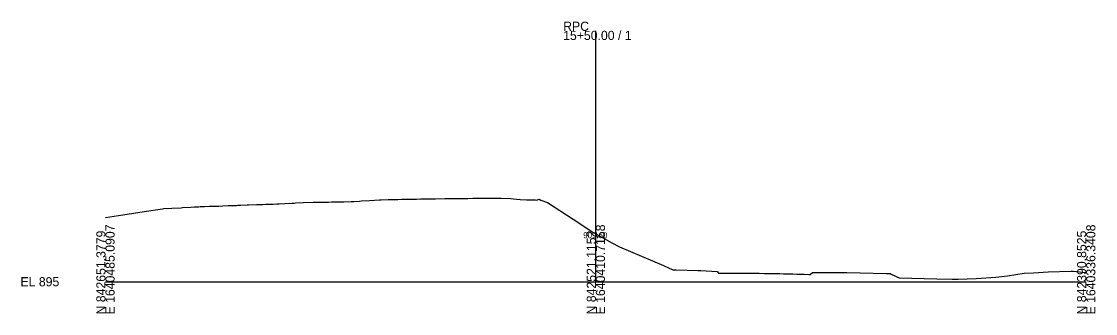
# Model space of a CAD drawing. Extents: x -26 to 1640245, y -10 to 842531.
# Drawn here: x 1274.3 to 1602.8, y 1490.3 to 1579.5 of the extents above; entities that cross this region are included whole.
import ezdxf

# ---------------------------------------------------------------- set-up
doc = ezdxf.new("R2010")
doc.units = 0
for name, color, linetype in [('Exist Cross Section Cell', 7, 'Continuous'), ('Exist XS Center Line Elevation Label', 7, 'Continuous'), ('Exist XS Ground Line', 7, 'Continuous')]:
    doc.layers.add(name, color=color, linetype=linetype)

msp = doc.modelspace()

# ---------------------------------------------------------------- linework, layer by layer
at = {"layer": 'Exist Cross Section Cell'}
for p, q in [((1450, 1500), (1450, 1576.62)), ((1300, 1500), (1450, 1500)), ((1450, 1500), (1600, 1500))]:
    msp.add_line(p, q, dxfattribs=at)
at = {"layer": 'Exist XS Ground Line'}
msp.add_lwpolyline([(1300, 1519.62), (1305.35, 1520.46), (1311.87, 1521.45), (1317.42, 1522.29), (1317.83, 1522.35), (1320.3, 1522.48), (1323.18, 1522.62), (1323.58, 1522.64), (1326.06, 1522.82), (1327.24, 1522.87), (1328.47, 1522.91), (1328.94, 1522.93), (1330.29, 1522.98), (1331.81, 1523.03), (1332.23, 1523.05), (1332.96, 1523.06), (1334.06, 1523.1), (1334.69, 1523.11), (1335.89, 1523.16), (1337.57, 1523.24), (1338.01, 1523.25), (1339.44, 1523.3), (1340.04, 1523.32), (1340.45, 1523.34), (1341.39, 1523.37), (1343.33, 1523.45), (1343.71, 1523.47), (1346.21, 1523.56), (1348.08, 1523.61), (1349.09, 1523.64), (1351.27, 1523.74), (1352.39, 1523.8), (1353.12, 1523.83), (1354.84, 1523.91), (1357.13, 1524.01), (1357.72, 1524.03), (1358.17, 1524.05), (1360.6, 1524.15), (1363.49, 1524.27), (1363.87, 1524.27), (1364.48, 1524.27), (1366.36, 1524.3), (1368.25, 1524.35), (1369.24, 1524.37), (1370.71, 1524.4), (1372.12, 1524.42), (1372.53, 1524.45), (1372.88, 1524.45), (1375.15, 1524.48), (1375.97, 1524.52), (1377.69, 1524.65), (1378.33, 1524.69), (1380.75, 1524.84), (1383.85, 1525), (1384.32, 1525.01), (1386.51, 1525.09), (1388.42, 1525.13), (1389.39, 1525.14), (1390.68, 1525.17), (1392.27, 1525.2), (1393.46, 1525.22), (1395.15, 1525.26), (1396.41, 1525.28), (1397.17, 1525.3), (1398.03, 1525.31), (1398.5, 1525.32), (1400.91, 1525.35), (1403.78, 1525.39), (1404.1, 1525.39), (1406.66, 1525.43), (1407.41, 1525.44), (1408.13, 1525.45), (1408.95, 1525.46), (1409.54, 1525.46), (1410.81, 1525.47), (1412.42, 1525.48), (1413.63, 1525.49), (1414.69, 1525.51), (1415.3, 1525.51), (1417.52, 1525.53), (1418.43, 1525.54), (1419.75, 1525.53), (1420.25, 1525.53), (1421.06, 1525.52), (1423.94, 1525.41), (1425.69, 1525.21), (1426.81, 1525.15), (1428.75, 1525.06), (1429.35, 1525.03), (1429.91, 1525.02), (1431, 1525), (1431.58, 1524.98), (1431.94, 1524.96), (1432.31, 1525.07), (1432.65, 1525.17), (1433.18, 1524.96), (1435.23, 1524.15), (1443.04, 1519.07), (1449.03, 1515.14), (1450, 1514.6), (1454.86, 1511.88), (1457.22, 1510.66), (1470.71, 1504.98), (1473.57, 1503.65), (1474.58, 1503.66), (1481.16, 1503.45), (1481.65, 1503.44), (1482.08, 1503.41), (1487.1, 1503.11), (1487.47, 1502.61), (1488.06, 1502.61), (1489.35, 1502.6), (1489.81, 1502.6), (1490.15, 1502.6), (1491.33, 1502.61), (1493.03, 1502.62), (1493.49, 1502.62), (1494.3, 1502.61), (1495.32, 1502.61), (1495.91, 1502.61), (1497.15, 1502.6), (1498.78, 1502.59), (1499.34, 1502.58), (1499.98, 1502.57), (1501.57, 1502.55), (1504.54, 1502.5), (1506.32, 1502.48), (1507.42, 1502.45), (1509.43, 1502.4), (1509.98, 1502.39), (1510.3, 1502.37), (1511.46, 1502.34), (1513.18, 1502.3), (1513.7, 1502.28), (1515.14, 1502.24), (1515.6, 1502.22), (1516.26, 1502.85), (1520.7, 1502.83), (1522.65, 1502.81), (1526.78, 1502.83), (1538.92, 1502.53), (1540.01, 1502.51), (1540.36, 1502.35), (1542.74, 1501.16), (1554.34, 1500.87), (1558.99, 1500.83), (1560.87, 1500.8), (1566.32, 1500.96), (1572.38, 1501.4), (1575.87, 1501.83), (1580.98, 1502.6), (1583.9, 1502.67), (1588.31, 1503.03), (1595.41, 1503.27), (1596.04, 1503.22), (1600, 1502.81)], dxfattribs=at)

# ---------------------------------------------------------------- texts
at = {"layer": 'Exist Cross Section Cell'}
for s, p in [('RPC', (1440, 1576.62)), ('15+50.00 / 1', (1440, 1573.82)), ('EL 895', (1274, 1498.6))]:
    msp.add_text(s, height=2.8, dxfattribs=at).set_placement(p)
for s, p in [('N 842651.3779', (1300, 1490)), ('E 1640485.0907', (1302.8, 1490)), ('N 842521.1152', (1450, 1490)), ('E 1640410.7158', (1452.8, 1490)), ('N 842390.8525', (1600, 1490)), ('E 1640336.3408', (1602.8, 1490))]:
    msp.add_text(s, height=2.8, rotation=90, dxfattribs=at).set_placement(p)
at = {"layer": 'Exist XS Center Line Elevation Label'}
msp.add_text('909.60', height=1.8, dxfattribs=at).set_placement((1446.14, 1513.3))

doc.saveas('drawing.dxf')
